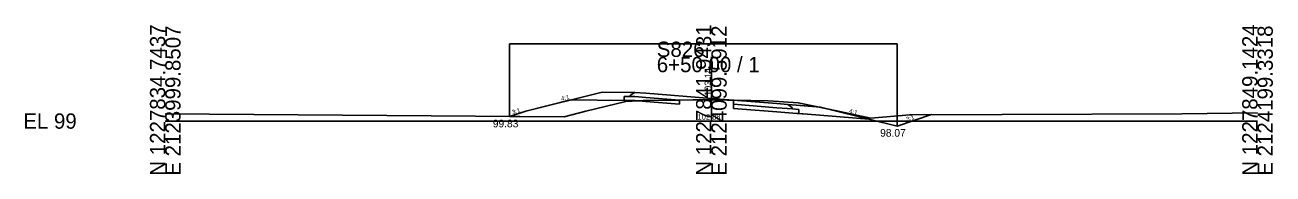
# Model space of a CAD drawing. Extents: x 2118382 to 2118616, y 1213030 to 1222057.
# Drawn here: x 2118381.9 to 2118610.4, y 1217030.1 to 1217057.4 of the extents above; entities that cross this region are included whole.
import ezdxf

# ---------------------------------------------------------------- set-up
doc = ezdxf.new("R2010")
doc.units = 0
for name, color, linetype in [('XS_CELL', 7, 'Continuous'), ('XS_M_DITCH', 7, 'Continuous'), ('XS_M_SHAPES_EARTHWORK', 7, 'Continuous'), ('XS_P_FINISHED_GRADE', 7, 'Continuous'), ('XS_P_FINISHED_GRADE_ELEV_TX', 7, 'Continuous'), ('XS_P_SUBGRADE_GRANULAR', 7, 'Continuous'), ('XS_P_SUBGRADE_LEVELING', 7, 'Continuous'), ('XS_P_SUBGRADE_PAVEMENT', 7, 'Continuous'), ('XS_P_TX_DCH', 7, 'Continuous'), ('XS_P_TX_FS_BS', 7, 'Continuous'), ('XS_X_GROUND', 7, 'Continuous'), ('XS_X_GROUND_TX', 7, 'Continuous')]:
    doc.layers.add(name, color=color, linetype=linetype)

msp = doc.modelspace()

# ---------------------------------------------------------------- linework, layer by layer
at = {"layer": 'XS_CELL'}
for p, q in [((2118507.6, 1217039.8), (2118507.6, 1217051.54)), ((2118407.6, 1217039.8), (2118507.6, 1217039.8)), ((2118507.6, 1217039.8), (2118607.6, 1217039.8))]:
    msp.add_line(p, q, dxfattribs=at)
at = {"layer": 'XS_M_DITCH'}
for p, q in [((2118470.66, 1217040.63), (2118470.66, 1217053.94)), ((2118470.66, 1217053.94), (2118541.6, 1217053.94)), ((2118541.6, 1217053.94), (2118541.6, 1217038.87))]:
    msp.add_line(p, q, dxfattribs=at)
at = {"layer": 'XS_M_SHAPES_EARTHWORK'}
for p, q in [((2118481.82, 1217043.67), (2118473.6, 1217041.61)), ((2118491.6, 1217043.57), (2118481.82, 1217043.67)), ((2118493.6, 1217043.55), (2118491.6, 1217043.57)), ((2118494.26, 1217043.5), (2118493.6, 1217043.55)), ((2118495.1, 1217043.55), (2118494.26, 1217043.5)), ((2118501.78, 1217043.64), (2118495.1, 1217043.55)), ((2118501.78, 1217042.9), (2118501.78, 1217043.64)), ((2118511.8, 1217043.61), (2118511.67, 1217043.61)), ((2118511.67, 1217043.61), (2118511.67, 1217042.87)), ((2118519.6, 1217042.99), (2118511.8, 1217043.61)), ((2118517.91, 1217043.52), (2118511.8, 1217043.61)), ((2118511.8, 1217043.61), (2118519.6, 1217042.99)), ((2118518.96, 1217043.47), (2118517.91, 1217043.52)), ((2118473.6, 1217041.61), (2118470.66, 1217040.63)), ((2118480.63, 1217040.55), (2118484.58, 1217041.61)), ((2118484.58, 1217041.61), (2118491.91, 1217043.39)), ((2118491.91, 1217043.39), (2118493.07, 1217043.42)), ((2118493.07, 1217043.42), (2118494.26, 1217043.5)), ((2118494.26, 1217043.5), (2118495.6, 1217043.39)), ((2118495.6, 1217043.39), (2118501.78, 1217042.9)), ((2118511.67, 1217042.87), (2118519.6, 1217042.24)), ((2118511.67, 1217042.87), (2118511.67, 1217042.12)), ((2118519.6, 1217042.24), (2118511.67, 1217042.87)), ((2118511.67, 1217042.12), (2118519.6, 1217041.49)), ((2118523.52, 1217043.14), (2118518.96, 1217043.47)), ((2118521.6, 1217042.84), (2118519.6, 1217042.99)), ((2118519.6, 1217042.99), (2118521.6, 1217042.84)), ((2118519.6, 1217042.24), (2118522.45, 1217042.02)), ((2118522.45, 1217042.02), (2118519.6, 1217042.24)), ((2118519.6, 1217041.49), (2118523.22, 1217041.21)), ((2118522.28, 1217042.32), (2118521.6, 1217042.84)), ((2118527.11, 1217042.4), (2118521.6, 1217042.84)), ((2118521.6, 1217042.84), (2118522.28, 1217042.32)), ((2118521.6, 1217042.84), (2118527.11, 1217042.4)), ((2118522.45, 1217042.02), (2118522.28, 1217042.32)), ((2118522.28, 1217042.32), (2118522.45, 1217042.02)), ((2118523.6, 1217041.93), (2118522.45, 1217042.02)), ((2118522.45, 1217042.02), (2118523.6, 1217041.93)), ((2118527.11, 1217042.4), (2118523.52, 1217043.14)), ((2118523.6, 1217041.18), (2118523.6, 1217041.93)), ((2118523.6, 1217041.93), (2118523.6, 1217041.18)), ((2118529.06, 1217042), (2118527.11, 1217042.4)), ((2118536.4, 1217040.17), (2118529.06, 1217042)), ((2118530.29, 1217041.75), (2118529.06, 1217042)), ((2118529.06, 1217042), (2118536.4, 1217040.17)), ((2118536.8, 1217040.34), (2118530.29, 1217041.75)), ((2118470.66, 1217040.63), (2118480.63, 1217040.55)), ((2118523.22, 1217041.21), (2118523.6, 1217041.18)), ((2118523.6, 1217041.18), (2118525.22, 1217041.05)), ((2118525.22, 1217041.05), (2118536.4, 1217040.17)), ((2118536.4, 1217040.17), (2118541.6, 1217038.87)), ((2118543.95, 1217040.93), (2118536.8, 1217040.34)), ((2118541.6, 1217038.87), (2118547.93, 1217040.98)), ((2118544.35, 1217040.97), (2118543.95, 1217040.93)), ((2118547.93, 1217040.98), (2118544.35, 1217040.97))]:
    msp.add_line(p, q, dxfattribs=at)
at = {"layer": 'XS_P_FINISHED_GRADE'}
for p, q in [((2118487.6, 1217045.11), (2118473.6, 1217041.61)), ((2118493.6, 1217045.05), (2118487.6, 1217045.11)), ((2118495.6, 1217044.89), (2118493.6, 1217045.05)), ((2118495.6, 1217044.89), (2118507.6, 1217043.94)), ((2118507.6, 1217043.94), (2118519.6, 1217042.99)), ((2118473.6, 1217041.61), (2118470.66, 1217040.63)), ((2118519.6, 1217042.99), (2118521.6, 1217042.84)), ((2118521.6, 1217042.84), (2118527.6, 1217042.36)), ((2118527.6, 1217042.36), (2118541.6, 1217038.87)), ((2118541.6, 1217038.87), (2118547.93, 1217040.98))]:
    msp.add_line(p, q, dxfattribs=at)
at = {"layer": 'XS_P_SUBGRADE_GRANULAR'}
for p, q in [((2118491.6, 1217043.57), (2118481.82, 1217043.67)), ((2118491.6, 1217043.57), (2118491.6, 1217044.32)), ((2118492.69, 1217044.31), (2118491.6, 1217044.32)), ((2118493.6, 1217043.55), (2118491.6, 1217043.57)), ((2118495.6, 1217043.39), (2118493.6, 1217043.55)), ((2118495.6, 1217043.39), (2118501.78, 1217042.9)), ((2118511.67, 1217042.12), (2118511.67, 1217042.87)), ((2118511.67, 1217042.12), (2118519.6, 1217041.49)), ((2118519.6, 1217041.49), (2118523.22, 1217041.21)), ((2118522.45, 1217042.02), (2118523.6, 1217041.93)), ((2118523.6, 1217041.18), (2118523.6, 1217041.93)), ((2118523.22, 1217041.21), (2118525.22, 1217041.05)), ((2118525.22, 1217041.05), (2118536.4, 1217040.17))]:
    msp.add_line(p, q, dxfattribs=at)
at = {"layer": 'XS_P_SUBGRADE_LEVELING'}
for p, q in [((2118504.25, 1217043.69), (2118501.78, 1217043.65)), ((2118506.02, 1217043.72), (2118504.25, 1217043.69)), ((2118506.81, 1217043.71), (2118506.02, 1217043.72)), ((2118507.6, 1217043.69), (2118506.81, 1217043.71)), ((2118507.6, 1217043.69), (2118510.55, 1217043.64)), ((2118510.55, 1217043.64), (2118511.47, 1217043.62)), ((2118511.47, 1217043.62), (2118511.67, 1217043.62))]:
    msp.add_line(p, q, dxfattribs=at)
at = {"layer": 'XS_P_SUBGRADE_PAVEMENT'}
for p, q in [((2118492.89, 1217044.65), (2118492.69, 1217044.31)), ((2118493.6, 1217044.3), (2118492.69, 1217044.31)), ((2118493.6, 1217045.05), (2118492.89, 1217044.65)), ((2118495.6, 1217044.14), (2118493.6, 1217044.3)), ((2118495.6, 1217044.14), (2118501.78, 1217043.65)), ((2118501.78, 1217042.9), (2118501.78, 1217043.65)), ((2118511.67, 1217042.87), (2118511.67, 1217043.62)), ((2118511.67, 1217042.87), (2118519.6, 1217042.24)), ((2118519.6, 1217042.24), (2118522.45, 1217042.02)), ((2118521.6, 1217042.84), (2118522.28, 1217042.32)), ((2118522.28, 1217042.32), (2118522.45, 1217042.02))]:
    msp.add_line(p, q, dxfattribs=at)
at = {"layer": 'XS_X_GROUND'}
for p, q in [((2118493.07, 1217043.42), (2118495.1, 1217043.55)), ((2118495.1, 1217043.55), (2118504.25, 1217043.68)), ((2118504.25, 1217043.68), (2118506.02, 1217043.71)), ((2118506.02, 1217043.71), (2118507.6, 1217043.68)), ((2118507.6, 1217043.68), (2118510.55, 1217043.63)), ((2118510.55, 1217043.63), (2118511.47, 1217043.62)), ((2118511.47, 1217043.62), (2118517.91, 1217043.52)), ((2118517.91, 1217043.52), (2118518.96, 1217043.47)), ((2118480.63, 1217040.55), (2118484.58, 1217041.61)), ((2118484.58, 1217041.61), (2118491.91, 1217043.39)), ((2118491.91, 1217043.39), (2118493.07, 1217043.42)), ((2118518.96, 1217043.47), (2118523.52, 1217043.14)), ((2118523.52, 1217043.14), (2118530.29, 1217041.75)), ((2118530.29, 1217041.75), (2118536.8, 1217040.34)), ((2118593.75, 1217041.1), (2118607.6, 1217041.3)), ((2118407.6, 1217041.15), (2118480.63, 1217040.55)), ((2118536.8, 1217040.34), (2118543.95, 1217040.93)), ((2118543.95, 1217040.93), (2118544.35, 1217040.97)), ((2118544.35, 1217040.97), (2118593.75, 1217041.1))]:
    msp.add_line(p, q, dxfattribs=at)

# ---------------------------------------------------------------- texts
at = {"layer": 'XS_CELL'}
for s, p in [('N 1227834.7437', (2118407.6, 1217029.8)), ('N 1227841.9431', (2118507.6, 1217029.8)), ('N 1227849.1424', (2118607.6, 1217029.8)), ('E 2123999.8507', (2118410.4, 1217029.8)), ('E 2124099.5912', (2118510.4, 1217029.8)), ('E 2124199.3318', (2118610.4, 1217029.8))]:
    msp.add_text(s, height=2.8, rotation=90, dxfattribs=at).set_placement(p)
for s, p in [('S826', (2118497.6, 1217051.54)), ('6+50.00 / 1', (2118497.6, 1217048.74)), ('EL 99', (2118381.6, 1217038.4))]:
    msp.add_text(s, height=2.8, dxfattribs=at).set_placement(p)
at = {"layer": 'XS_P_FINISHED_GRADE_ELEV_TX'}
msp.add_text(' 103.14', height=1.25, rotation=90, dxfattribs=at).set_placement((2118507.6, 1217043.94))
at = {"layer": 'XS_P_TX_DCH'}
for s, p in [('99.83', (2118467.57, 1217038.65)), ('98.07', (2118538.5, 1217036.94))]:
    msp.add_text(s, height=1.4, dxfattribs=at).set_placement(p)
at = {"layer": 'XS_P_TX_FS_BS'}
for s, rotation, p in [('4:1', 14.0157, (2118480.18, 1217043.48)), ('3:1', 18.4087, (2118471.23, 1217041)), ('4:1', 345.988, (2118532.76, 1217041.29)), ('3:1', 18.404, (2118543.39, 1217039.72))]:
    msp.add_text(s, height=0.8, rotation=rotation, dxfattribs=at).set_placement(p)
at = {"layer": 'XS_X_GROUND_TX'}
msp.add_text('102.88', height=1, dxfattribs=at).set_placement((2118505.05, 1217040.06))

doc.saveas('drawing.dxf')
